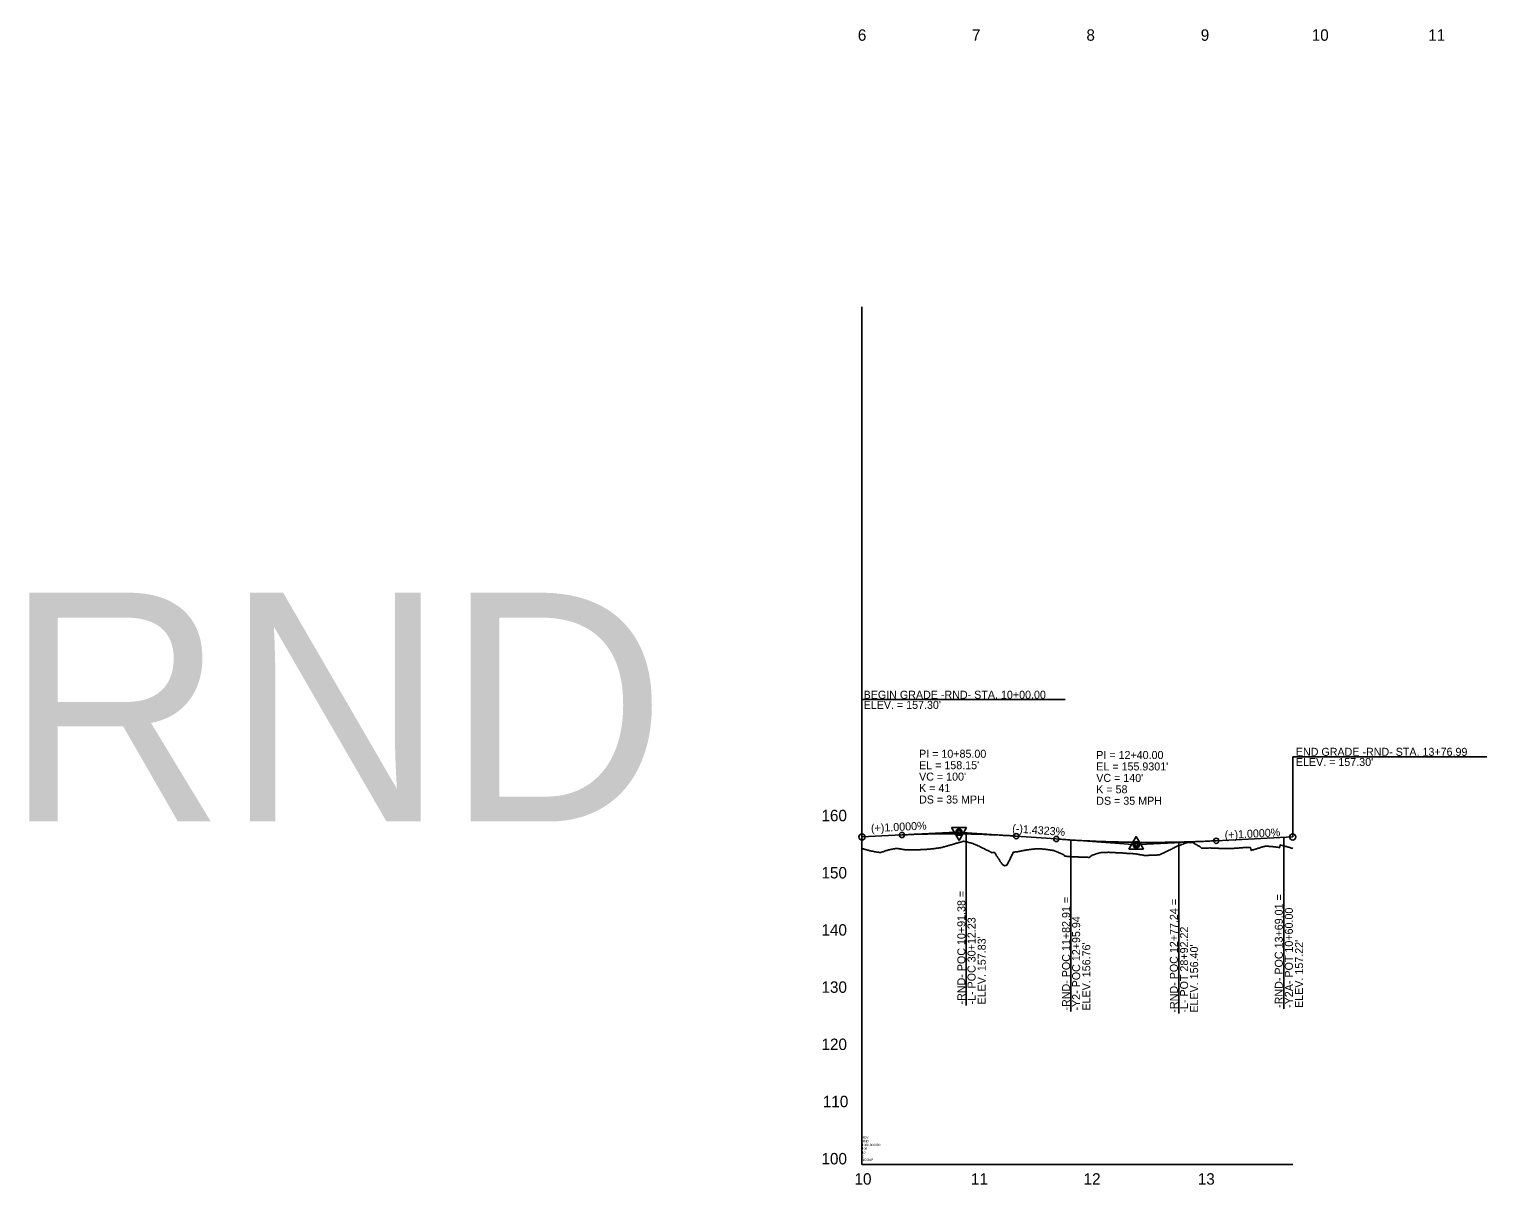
# Model space of a CAD drawing. Extents: x 1778432 to 1784301, y 601022 to 621789.
# Drawn here: x 1779415 to 1780690, y 619022 to 620032 of the extents above; entities that cross this region are included whole.
import ezdxf

# ---------------------------------------------------------------- set-up
doc = ezdxf.new("R2010")
doc.units = 0
for name, color, linetype in [('Exist Profile Cell', 7, 'Continuous'), ('Exist Vertical Profile Ground Line', 7, 'Continuous'), ('Exist Vertical Profile Horizontal Axis Label Major', 7, 'Continuous'), ('Exist Vertical Profile Vertical Axis Label', 7, 'Continuous'), ('Prop PFL Text', 7, 'Continuous'), ('Prop PFL VPI Symbol CELL', 7, 'Continuous'), ('Prop Vertical Profile Curve Label', 7, 'Continuous'), ('Prop Vertical Profile Grade', 7, 'Continuous'), ('Prop Vertical Profile Grade Label', 7, 'Continuous'), ('Prop VPI Label', 7, 'Continuous')]:
    doc.layers.add(name, color=color, linetype=linetype)

msp = doc.modelspace()

# ---------------------------------------------------------------- linework, layer by layer
at = {"layer": 'Exist Profile Cell'}
for q in [(1780143, 619789.2), (1780520, 619039.2), (1780143, 619039.2)]:
    msp.add_line((1780143, 619039.2), q, dxfattribs=at)
at = {"layer": 'Exist Vertical Profile Ground Line'}
msp.add_lwpolyline([(1780143, 619315.6), (1780143.6, 619315.4), (1780144.3, 619315.2), (1780145, 619315), (1780145.7, 619314.8), (1780146.4, 619314.6), (1780147.1, 619314.4), (1780147.8, 619314.2), (1780148.7, 619314), (1780149.2, 619313.8), (1780149.8, 619313.6), (1780150.8, 619313.4), (1780151.2, 619313.3), (1780151.9, 619313.2), (1780152.6, 619313.1), (1780153.3, 619313), (1780154, 619312.8), (1780154.7, 619312.7), (1780155.3, 619312.6), (1780156, 619312.5), (1780156.7, 619312.4), (1780157.4, 619312.3), (1780158.1, 619312.2), (1780158.8, 619312.1), (1780159.5, 619312.2), (1780160.2, 619312.4), (1780161.1, 619312.6), (1780161.5, 619312.7), (1780162.2, 619312.9), (1780162.9, 619313.2), (1780163.6, 619313.4), (1780164.3, 619313.7), (1780165, 619313.9), (1780165.7, 619314.2), (1780166.3, 619314.4), (1780167, 619314.5), (1780167.7, 619314.7), (1780168.4, 619314.8), (1780169.1, 619314.9), (1780169.8, 619315), (1780170.5, 619315.2), (1780171.2, 619315.3), (1780171.9, 619315.4), (1780172.2, 619315.5), (1780172.5, 619315.5), (1780173.2, 619315.5), (1780173.9, 619315.6), (1780174.6, 619315.5), (1780175.3, 619315.4), (1780176.1, 619315.3), (1780176.7, 619315.2), (1780177.4, 619315.1), (1780178, 619314.9), (1780178.7, 619314.8), (1780179.4, 619314.7), (1780180.1, 619314.6), (1780180.8, 619314.5), (1780181.1, 619314.4), (1780181.5, 619314.4), (1780182.2, 619314.4), (1780182.9, 619314.4), (1780183.5, 619314.4), (1780184.2, 619314.4), (1780184.9, 619314.4), (1780185.6, 619314.5), (1780186.3, 619314.5), (1780187, 619314.5), (1780187.7, 619314.5), (1780188.4, 619314.5), (1780189.1, 619314.5), (1780189.7, 619314.5), (1780190.4, 619314.5), (1780191.1, 619314.5), (1780191.8, 619314.5), (1780192.5, 619314.5), (1780193.2, 619314.5), (1780193.9, 619314.5), (1780194.6, 619314.6), (1780195.2, 619314.6), (1780195.9, 619314.6), (1780196.6, 619314.6), (1780197.2, 619314.6), (1780198, 619314.7), (1780198.7, 619314.7), (1780199.4, 619314.8), (1780200.1, 619314.9), (1780200.7, 619314.9), (1780201.4, 619315), (1780202.1, 619315.1), (1780202.8, 619315.1), (1780203.5, 619315.2), (1780204.2, 619315.3), (1780204.6, 619315.3), (1780204.9, 619315.3), (1780205.6, 619315.4), (1780206.3, 619315.5), (1780206.9, 619315.6), (1780207.6, 619315.7), (1780208.3, 619315.8), (1780209, 619315.9), (1780209.7, 619316), (1780210.4, 619316.1), (1780211.1, 619316.2), (1780211.8, 619316.3), (1780212.4, 619316.4), (1780213.2, 619316.5), (1780213.8, 619316.7), (1780214.5, 619316.9), (1780215.2, 619317.1), (1780215.9, 619317.3), (1780216.6, 619317.5), (1780217.3, 619317.7), (1780217.9, 619317.9), (1780218.6, 619318.1), (1780219.3, 619318.3), (1780220, 619318.5), (1780220.7, 619318.7), (1780221.4, 619318.9), (1780222.1, 619319.1), (1780222.8, 619319.3), (1780223.4, 619319.5), (1780224.1, 619319.7), (1780224.8, 619319.9), (1780225.5, 619320.1), (1780226.2, 619320.3), (1780226.9, 619320.5), (1780227.6, 619320.7), (1780228.3, 619320.9), (1780229, 619321), (1780229.6, 619321.2), (1780230.3, 619321.4), (1780231, 619321.6), (1780231.9, 619321.9), (1780232.4, 619321.8), (1780233.2, 619321.7), (1780233.8, 619321.7), (1780234.5, 619321.5), (1780235.1, 619321.3), (1780235.8, 619321.1), (1780236.5, 619320.9), (1780237.5, 619320.6), (1780237.9, 619320.5), (1780238.8, 619320.2), (1780239.3, 619320.1), (1780240, 619319.8), (1780240.6, 619319.6), (1780241.3, 619319.3), (1780242.2, 619319.1), (1780242.7, 619318.9), (1780243.6, 619318.5), (1780244.1, 619318.3), (1780244.8, 619317.9), (1780245.5, 619317.5), (1780246.4, 619317), (1780246.9, 619316.8), (1780247.5, 619316.5), (1780248.2, 619316.2), (1780248.9, 619315.8), (1780249.6, 619315.5), (1780250.3, 619315.2), (1780250.6, 619315), (1780251, 619314.8), (1780251.7, 619314.5), (1780252.3, 619314.1), (1780253.1, 619313.7), (1780253.7, 619313.4), (1780254.1, 619313.2), (1780254.5, 619313.1), (1780255.3, 619312.6), (1780255.8, 619312.4), (1780256.8, 619311.9), (1780257.3, 619312), (1780258, 619312.1), (1780258.5, 619312.2), (1780259.1, 619312.2), (1780259.9, 619310.8), (1780260.8, 619309.2), (1780261.3, 619308.5), (1780262, 619307.4), (1780262.7, 619306.4), (1780263.3, 619305.3), (1780264, 619304.2), (1780264.7, 619303.2), (1780265.3, 619302.3), (1780266.1, 619301.6), (1780266.8, 619301.1), (1780267.6, 619300.4), (1780268.2, 619300.6), (1780268.9, 619300.8), (1780269.5, 619301), (1780270.1, 619301.2), (1780270.5, 619302.1), (1780270.9, 619302.9), (1780271.6, 619304.4), (1780272.3, 619305.8), (1780273, 619307.2), (1780273.7, 619308.7), (1780274.4, 619310.1), (1780275, 619311.4), (1780275.5, 619312.4), (1780276.4, 619312.5), (1780277.1, 619312.6), (1780277.8, 619312.7), (1780278.5, 619312.7), (1780279.2, 619312.8), (1780279.9, 619312.9), (1780280.5, 619312.9), (1780281.2, 619313.1), (1780281.9, 619313.2), (1780282.6, 619313.4), (1780283.3, 619313.6), (1780284, 619313.7), (1780284.8, 619313.9), (1780285.4, 619314), (1780286.1, 619314.1), (1780286.7, 619314.2), (1780287.4, 619314.3), (1780288.1, 619314.4), (1780288.8, 619314.5), (1780289.5, 619314.6), (1780290.2, 619314.7), (1780290.9, 619314.8), (1780291.6, 619314.9), (1780292.2, 619315), (1780292.9, 619315), (1780293.6, 619315.1), (1780294.3, 619315.2), (1780295, 619315.2), (1780296, 619315.2), (1780296.4, 619315.2), (1780297.1, 619315.3), (1780297.7, 619315.3), (1780298.4, 619315.3), (1780299.1, 619315.2), (1780299.8, 619315.2), (1780300.5, 619315.2), (1780301.2, 619315.1), (1780301.9, 619315), (1780302.6, 619315), (1780303.2, 619314.9), (1780303.9, 619314.8), (1780304.6, 619314.7), (1780305.3, 619314.6), (1780306, 619314.5), (1780306.7, 619314.4), (1780307.4, 619314.3), (1780308.1, 619314.2), (1780308.8, 619314.1), (1780309.4, 619314), (1780310.1, 619313.9), (1780310.8, 619313.8), (1780311.5, 619313.5), (1780312.2, 619313.2), (1780312.9, 619312.9), (1780313.6, 619312.6), (1780314.3, 619312.3), (1780314.9, 619312.1), (1780315.6, 619311.8), (1780316.3, 619311.5), (1780317, 619311.2), (1780317.7, 619310.9), (1780318.4, 619310.6), (1780318.8, 619310.4), (1780319.1, 619310.2), (1780319.8, 619309.7), (1780320.4, 619308.9), (1780321.1, 619308.8), (1780321.8, 619308.8), (1780322.5, 619308.7), (1780323.2, 619308.6), (1780323.9, 619308.6), (1780324.6, 619308.5), (1780325.3, 619308.4), (1780326.1, 619308.4), (1780326.6, 619308.3), (1780327.3, 619308.3), (1780328, 619308.3), (1780328.7, 619308.3), (1780329.4, 619308.3), (1780330.1, 619308.2), (1780330.8, 619308.2), (1780331.5, 619308.2), (1780331.8, 619308.2), (1780332.1, 619308.2), (1780332.8, 619308.1), (1780333.5, 619308.1), (1780334.2, 619308.1), (1780334.9, 619308.1), (1780335.6, 619308), (1780336.3, 619308), (1780337, 619308), (1780337.6, 619308), (1780338.5, 619307.9), (1780339, 619307.9), (1780339.7, 619307.9), (1780340.4, 619307.9), (1780341.1, 619307.8), (1780341.8, 619307.8), (1780342.1, 619307.8), (1780342.7, 619308.5), (1780343.2, 619308.8), (1780344, 619309.4), (1780344.5, 619309.6), (1780345.2, 619309.9), (1780345.9, 619310.1), (1780346.6, 619310.3), (1780347.3, 619310.6), (1780348, 619310.8), (1780348.7, 619311.1), (1780349.3, 619311.3), (1780350, 619311.5), (1780350.7, 619311.7), (1780351.4, 619311.9), (1780352.2, 619312), (1780352.8, 619312), (1780353.5, 619312), (1780354.2, 619312.1), (1780354.8, 619312.1), (1780355.5, 619312.1), (1780356.2, 619312.1), (1780356.9, 619312.2), (1780357.6, 619312.2), (1780358.3, 619312.3), (1780359, 619312.3), (1780359.7, 619312.2), (1780360.3, 619312.2), (1780361, 619312.1), (1780361.8, 619312.1), (1780362.4, 619312.1), (1780363.1, 619312), (1780363.8, 619312), (1780364.5, 619312), (1780365.2, 619311.9), (1780365.9, 619311.9), (1780366.5, 619311.9), (1780366.8, 619311.9), (1780367.2, 619311.9), (1780367.9, 619311.8), (1780368.6, 619311.8), (1780369.3, 619311.8), (1780370, 619311.7), (1780370.7, 619311.7), (1780371.4, 619311.6), (1780372, 619311.5), (1780372.7, 619311.5), (1780373.1, 619311.4), (1780373.4, 619311.4), (1780374.1, 619311.4), (1780374.8, 619311.3), (1780375.5, 619311.3), (1780376.2, 619311.3), (1780376.9, 619311.2), (1780377.5, 619311.2), (1780378.2, 619311.2), (1780378.9, 619311.1), (1780379.6, 619311.1), (1780380.3, 619311), (1780381, 619310.9), (1780381.7, 619310.9), (1780382.5, 619310.8), (1780383.1, 619310.7), (1780383.7, 619310.6), (1780384.4, 619310.5), (1780385.1, 619310.4), (1780385.8, 619310.2), (1780386.5, 619310.1), (1780387.3, 619310), (1780387.9, 619309.9), (1780388.6, 619309.8), (1780389.2, 619309.6), (1780389.9, 619309.5), (1780390.6, 619309.5), (1780391.3, 619309.5), (1780392, 619309.5), (1780392.7, 619309.5), (1780393.4, 619309.5), (1780394.1, 619309.6), (1780394.7, 619309.6), (1780395.4, 619309.6), (1780396.1, 619309.7), (1780396.8, 619309.7), (1780397.5, 619309.7), (1780398.2, 619309.7), (1780398.9, 619309.8), (1780399.6, 619309.8), (1780400.2, 619309.8), (1780400.9, 619309.8), (1780401.6, 619309.9), (1780402.3, 619309.9), (1780403.2, 619309.9), (1780403.8, 619310.2), (1780404.4, 619310.5), (1780404.8, 619310.7), (1780405.1, 619310.9), (1780405.8, 619311.2), (1780406.4, 619311.5), (1780407.1, 619311.8), (1780407.8, 619312.2), (1780408.2, 619312.4), (1780408.8, 619312.7), (1780409.2, 619312.9), (1780409.9, 619313.2), (1780410.6, 619313.5), (1780410.9, 619313.7), (1780411.4, 619313.9), (1780411.9, 619314.2), (1780412.6, 619314.5), (1780413.4, 619314.9), (1780414, 619315.1), (1780414.8, 619315.6), (1780415.4, 619315.9), (1780416.1, 619316.2), (1780416.5, 619316.5), (1780417.6, 619316.9), (1780418.1, 619317.2), (1780418.9, 619317.5), (1780419.5, 619317.8), (1780420.2, 619318), (1780420.9, 619318.3), (1780421.6, 619318.6), (1780422.3, 619318.9), (1780422.6, 619319), (1780423, 619319.2), (1780423.9, 619319.5), (1780424.3, 619319.7), (1780425.2, 619320), (1780425.7, 619320.2), (1780426.7, 619320.5), (1780427.1, 619320.6), (1780427.8, 619320.7), (1780428.5, 619320.7), (1780429.1, 619320.7), (1780429.8, 619320.7), (1780430.5, 619320.7), (1780431.2, 619320.7), (1780431.9, 619320.7), (1780432.4, 619320.7), (1780433.3, 619320.2), (1780434, 619319.9), (1780434.6, 619319.5), (1780435.3, 619319.1), (1780436, 619318.7), (1780436.7, 619318.3), (1780437.4, 619317.9), (1780437.7, 619317.7), (1780438.1, 619317.5), (1780438.8, 619316.9), (1780439.5, 619316.4), (1780440.2, 619315.8), (1780440.8, 619315.8), (1780441.5, 619315.9), (1780442.2, 619315.9), (1780442.9, 619315.9), (1780443.6, 619315.9), (1780444.3, 619316), (1780445, 619316), (1780445.7, 619316), (1780446.3, 619316), (1780447.3, 619316.1), (1780447.7, 619316.1), (1780448.4, 619316), (1780449.1, 619316), (1780449.8, 619316), (1780450.5, 619316), (1780451.2, 619315.9), (1780451.8, 619315.9), (1780452.5, 619315.9), (1780453.2, 619315.9), (1780454.1, 619315.8), (1780454.6, 619315.8), (1780455.3, 619315.7), (1780456, 619315.7), (1780456.7, 619315.6), (1780457.3, 619315.6), (1780458, 619315.5), (1780458.9, 619315.5), (1780459.4, 619315.5), (1780460.1, 619315.5), (1780460.8, 619315.5), (1780461.5, 619315.5), (1780462.2, 619315.5), (1780462.9, 619315.5), (1780463.5, 619315.5), (1780464.2, 619315.5), (1780464.9, 619315.5), (1780465.3, 619315.6), (1780465.6, 619315.6), (1780466.3, 619315.6), (1780467, 619315.7), (1780467.7, 619315.7), (1780468.4, 619315.7), (1780469, 619315.8), (1780469.7, 619315.8), (1780470.4, 619315.9), (1780471.1, 619315.9), (1780471.8, 619316), (1780472.5, 619316), (1780473.2, 619316.1), (1780473.9, 619316.1), (1780474.5, 619316.2), (1780475.2, 619316.3), (1780475.9, 619316.3), (1780476.6, 619316.4), (1780477.4, 619316.4), (1780478, 619316.4), (1780478.7, 619316.4), (1780479.4, 619316.4), (1780480.1, 619316.4), (1780480.7, 619316.4), (1780481.4, 619316.4), (1780482.1, 619316.4), (1780482.9, 619316.4), (1780483.4, 619313.9), (1780484.2, 619314.1), (1780485.1, 619314.4), (1780485.6, 619314.5), (1780486.2, 619314.7), (1780486.9, 619314.9), (1780487.6, 619315.1), (1780488.3, 619315.3), (1780489, 619315.5), (1780489.7, 619315.8), (1780490.4, 619316), (1780491.1, 619316.2), (1780491.7, 619316.4), (1780492.4, 619316.6), (1780493.1, 619316.8), (1780493.8, 619317), (1780494.5, 619317.2), (1780495.2, 619317.4), (1780495.9, 619317.6), (1780496.2, 619317.7), (1780496.6, 619317.7), (1780497.2, 619317.6), (1780497.9, 619317.5), (1780498.6, 619317.5), (1780499.3, 619317.4), (1780500, 619317.4), (1780500.7, 619317.3), (1780501.4, 619317.2), (1780502.1, 619317.2), (1780502.8, 619317.1), (1780503.7, 619317), (1780504.1, 619316.9), (1780504.8, 619316.9), (1780505.5, 619316.8), (1780506.2, 619316.7), (1780506.8, 619316.7), (1780507.6, 619316.4), (1780508.4, 619316.2), (1780508.8, 619318.7), (1780509.6, 619318.5), (1780510.6, 619318.3), (1780511, 619318.2), (1780511.7, 619318), (1780512.4, 619317.8), (1780513.1, 619317.6), (1780513.8, 619317.4), (1780514.4, 619317.2), (1780515.1, 619317), (1780515.8, 619316.8), (1780516.5, 619316.6), (1780517.2, 619316.4), (1780517.9, 619316.2), (1780518.6, 619316), (1780519.3, 619315.8), (1780519.9, 619315.6)], dxfattribs=at)
at = {"layer": 'Prop PFL VPI Symbol CELL'}
for p, q in [((1780228, 619322.6), (1780221.5, 619333.8)), ((1780234.5, 619333.8), (1780221.5, 619333.8)), ((1780228, 619322.6), (1780234.5, 619333.8)), ((1780382.9, 619326.2), (1780376.5, 619315)), ((1780382.9, 619326.2), (1780389.4, 619315)), ((1780376.5, 619315), (1780389.4, 619315))]:
    msp.add_line(p, q, dxfattribs=at)
for centre, radius in [((1780228, 619330.1), 1.75), ((1780228, 619330.1), 1.2), ((1780382.9, 619318.7), 1.75), ((1780382.9, 619318.7), 1.2)]:
    msp.add_circle(centre, radius, dxfattribs=at)
at = {"layer": 'Prop Vertical Profile Curve Label'}
for centre in [(1780178, 619327.4), (1780278, 619326.4), (1780313, 619323.9), (1780453, 619322.3)]:
    msp.add_circle(centre, 2.25, dxfattribs=at)
at = {"layer": 'Prop Vertical Profile Grade'}
for p, q in [((1780143, 619325.7), (1780178, 619327.4)), ((1780278, 619326.4), (1780313, 619323.9)), ((1780453, 619322.3), (1780519.9, 619325.7))]:
    msp.add_line(p, q, dxfattribs=at)
for points in [[(1780178, 619327.4), (1780180, 619327.5), (1780182, 619327.6), (1780184, 619327.7), (1780186, 619327.8), (1780188, 619327.9), (1780190, 619328), (1780192, 619328), (1780194, 619328.1), (1780196, 619328.1), (1780198, 619328.2), (1780200, 619328.2), (1780202, 619328.3), (1780204, 619328.3), (1780206, 619328.4), (1780208, 619328.4), (1780210, 619328.4), (1780212, 619328.4), (1780214, 619328.5), (1780216, 619328.5), (1780218, 619328.5), (1780220, 619328.5), (1780222, 619328.5), (1780224, 619328.5), (1780226, 619328.4), (1780228, 619328.4), (1780230, 619328.4), (1780232, 619328.4), (1780234, 619328.3), (1780236, 619328.3), (1780238, 619328.3), (1780240, 619328.2), (1780242, 619328.2), (1780244, 619328.1), (1780246, 619328), (1780248, 619328), (1780250, 619327.9), (1780252, 619327.8), (1780254, 619327.7), (1780256, 619327.6), (1780258, 619327.6), (1780260, 619327.5), (1780262, 619327.4), (1780264, 619327.2), (1780266, 619327.1), (1780268, 619327), (1780270, 619326.9), (1780272, 619326.8), (1780274, 619326.6), (1780276, 619326.5), (1780278, 619326.4)], [(1780313, 619323.9), (1780315.8, 619323.7), (1780318.6, 619323.5), (1780321.4, 619323.3), (1780324.2, 619323.1), (1780327, 619322.9), (1780329.8, 619322.8), (1780332.6, 619322.6), (1780335.4, 619322.5), (1780338.2, 619322.3), (1780341, 619322.2), (1780343.8, 619322.1), (1780346.6, 619321.9), (1780349.4, 619321.8), (1780352.2, 619321.7), (1780355, 619321.6), (1780357.8, 619321.5), (1780360.6, 619321.4), (1780363.4, 619321.3), (1780366.2, 619321.3), (1780369, 619321.2), (1780371.8, 619321.1), (1780374.6, 619321.1), (1780377.4, 619321), (1780380.2, 619321), (1780383, 619321), (1780385.8, 619320.9), (1780388.6, 619320.9), (1780391.4, 619320.9), (1780394.2, 619320.9), (1780397, 619320.9), (1780399.8, 619320.9), (1780402.6, 619320.9), (1780405.4, 619320.9), (1780408.2, 619321), (1780411, 619321), (1780413.8, 619321), (1780416.6, 619321.1), (1780419.4, 619321.2), (1780422.2, 619321.2), (1780425, 619321.3), (1780427.8, 619321.4), (1780430.6, 619321.4), (1780433.4, 619321.5), (1780436.2, 619321.6), (1780439, 619321.7), (1780441.8, 619321.8), (1780444.6, 619322), (1780447.4, 619322.1), (1780450.2, 619322.2), (1780453, 619322.3)]]:
    msp.add_spline(points, degree=3, dxfattribs=at)
at = {"layer": 'Prop VPI Label'}
for p, q in [((1780143, 619325.7), (1780143, 619445.7)), ((1780143, 619445.7), (1780320.8, 619445.7)), ((1780519.9, 619325.7), (1780519.9, 619395.7)), ((1780519.9, 619395.7), (1780689.7, 619395.7)), ((1780178, 619327.4), (1780225.2, 619329.8)), ((1780278, 619326.4), (1780230.7, 619329.7)), ((1780234.3, 619328.3), (1780234.3, 619178.3)), ((1780313, 619323.9), (1780380.2, 619319)), ((1780325.9, 619323), (1780325.9, 619173)), ((1780453, 619322.3), (1780385.7, 619319)), ((1780420.2, 619321.2), (1780420.2, 619171.2)), ((1780512, 619325.3), (1780512, 619175.3))]:
    msp.add_line(p, q, dxfattribs=at)
for centre in [(1780228, 619329.9), (1780143, 619325.7), (1780383, 619318.8), (1780519.9, 619325.7)]:
    msp.add_circle(centre, 2.75, dxfattribs=at)

# ---------------------------------------------------------------- texts
at = {"layer": 'Exist Profile Cell'}
for s, p in [('RDY', (1780143, 619061.9)), ('RND', (1780143, 619058.7)), ('1000.000000', (1780143, 619055.4)), ('100', (1780143, 619052.2)), ('10', (1780143, 619048.9)), ('2', (1780143, 619045.7)), ('NOGAP', (1780143, 619042.4))]:
    msp.add_text(s, height=2, dxfattribs=at).set_placement(p)
at = {"layer": 'Exist Vertical Profile Horizontal Axis Label Major'}
for s, p in [('6', (1780139.4, 620021.7)), ('7', (1780239.3, 620021.7)), ('8', (1780339.4, 620021.7)), ('9', (1780439.4, 620021.7)), ('10', (1780536.5, 620021.7)), ('11', (1780638.4, 620021.7)), ('10', (1780136.5, 619021.7)), ('11', (1780238.4, 619021.7)), ('12', (1780336.9, 619021.7)), ('13', (1780436.8, 619021.7))]:
    msp.add_text(s, height=10, dxfattribs=at).set_placement(p)
at = {"layer": 'Exist Vertical Profile Vertical Axis Label'}
for s, p in [('160', (1780107.6, 619339.4)), ('150', (1780107.6, 619289.4)), ('140', (1780107.6, 619239.4)), ('130', (1780107.6, 619189.4)), ('120', (1780107.6, 619139.4)), ('110', (1780108.8, 619089.4)), ('100', (1780107.6, 619039.4))]:
    msp.add_text(s, height=10, dxfattribs=at).set_placement(p)
at = {"layer": 'Prop PFL Text'}
msp.add_text('RND', height=200, dxfattribs=at).set_placement((1779392.6, 619339.2))
at = {"layer": 'Prop Vertical Profile Curve Label'}
for s, p in [("VC = 100'", (1780193, 619374.9)), ("VC = 140'", (1780348, 619373.8)), ('K = 41', (1780193, 619364.9)), ('K = 58', (1780348, 619363.8)), ('DS = 35 MPH', (1780193, 619354.9)), ('DS = 35 MPH', (1780348, 619353.8))]:
    msp.add_text(s, height=7, dxfattribs=at).set_placement(p)
at = {"layer": 'Prop Vertical Profile Grade Label'}
for s, rotation, p in [('(+)1.0000%', 2.8624, (1780151.1, 619329.8)), ('(-)1.4323%', 355.9041, (1780274.3, 619329.8)), ('(+)1.0000%', 2.8624, (1780460.5, 619323.9))]:
    msp.add_text(s, height=7, rotation=rotation, dxfattribs=at).set_placement(p)
at = {"layer": 'Prop VPI Label'}
for s, p in [('BEGIN GRADE -RND- STA. 10+00.00', (1780144.5, 619446.5)), ("ELEV. = 157.30'", (1780144.5, 619437.6)), ('PI = 10+85.00', (1780193, 619394.9)), ('PI = 12+40.00', (1780348, 619393.8)), ('END GRADE -RND- STA. 13+76.99', (1780522.6, 619396.6)), ("ELEV. = 157.30'", (1780522.6, 619387.7)), ("EL = 158.15'", (1780193, 619384.9)), ("EL = 155.9301'", (1780348, 619383.8))]:
    msp.add_text(s, height=7, dxfattribs=at).set_placement(p)
for s, p in [('-RND- POC 10+91.38 =', (1780233.5, 619179.2)), ('-RND- POC 11+82.91 =', (1780325.1, 619173.9)), ('-RND- POC 12+77.24 =', (1780419.4, 619172.1)), ('-RND- POC 13+69.01 =', (1780511.2, 619176.2)), ('-L- POC 30+12.23', (1780242.4, 619179.2)), ('-Y2- POC 12+95.94', (1780333.9, 619173.9)), ('-Y2A- POT 10+60.00', (1780520, 619176.2)), ('-L- POT 28+92.22', (1780428.3, 619172.1)), ("ELEV. 157.83'", (1780251.3, 619179.2)), ("ELEV. 156.76'", (1780342.8, 619173.9)), ("ELEV. 156.40'", (1780437.1, 619172.1)), ("ELEV. 157.22'", (1780528.9, 619176.2))]:
    msp.add_text(s, height=7, rotation=90, dxfattribs=at).set_placement(p)

doc.saveas('drawing.dxf')
